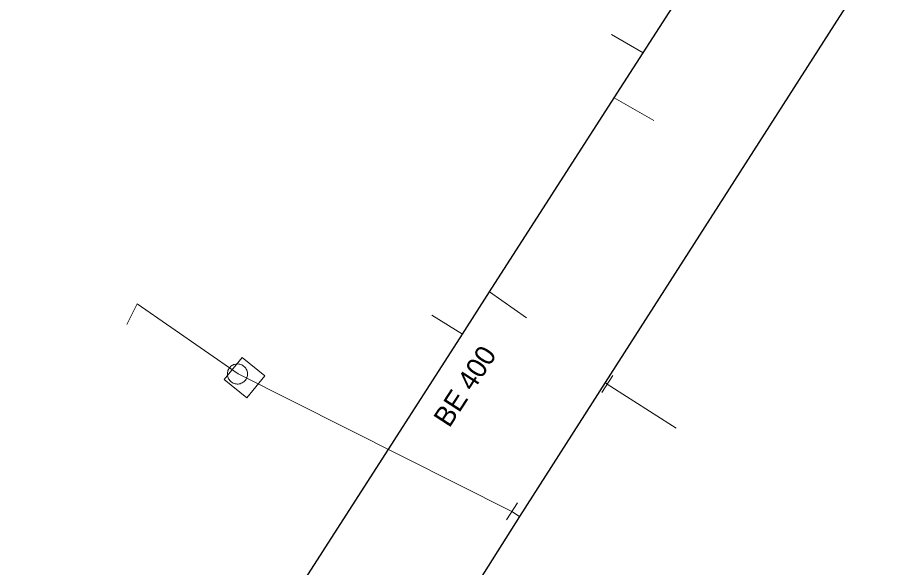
# Model space of a CAD drawing. Extents: x -791337 to -790755, y -988454 to -987923.
# Drawn here: x -791228.7 to -791185.71, y -988043.56 to -988016.22 of the extents above; entities that cross this region are included whole.
import ezdxf

# ---------------------------------------------------------------- set-up
doc = ezdxf.new("R2010")
doc.units = 0
doc.header["$LTSCALE"] = 0.4
for name, color, linetype, lineweight in [('1', 7, 'Continuous', 13), ('11', 7, 'Continuous', 13), ('13', 7, 'Continuous', 13), ('14', 7, 'Continuous', 25), ('17', 7, 'Continuous', 25), ('2', 7, 'Continuous', 13), ('23', 7, 'Continuous', 13), ('34', 7, 'Continuous', 13)]:
    doc.layers.add(name, color=color, linetype=linetype, lineweight=lineweight)

msp = doc.modelspace()

# ---------------------------------------------------------------- linework, layer by layer
at = {"layer": '11'}
for p, q in [((-791199.175, -988017.077), (-791197.614, -988017.994)), ((-791197.071, -988021.344), (-791199.047, -988020.224)), ((-791203.4, -988031.154), (-791205.24, -988029.863)), ((-791208.105, -988031.022), (-791206.587, -988031.96))]:
    msp.add_line(p, q, dxfattribs=at)
at = {"layer": '13'}
for p, q in [((-791204.128, -988040.763), (-791217.731, -988033.931)), ((-791199.39, -988034.44), (-791195.969, -988036.629))]:
    msp.add_line(p, q, dxfattribs=at)
msp.add_lwpolyline([(-791217.731, -988033.931), (-791222.747, -988030.456), (-791223.259, -988031.478)], dxfattribs=at)
at = {"layer": '14', "lineweight": 13}
for p, q in [((-791199.496, -988034.364), (-791199.391, -988034.44)), ((-791203.749, -988041.021), (-791204.128, -988040.763))]:
    msp.add_line(p, q, dxfattribs=at)
at = {"layer": '14'}
msp.add_lwpolyline([(-791220.36, -988053.399), (-791218.616, -988050.685), (-791216.914, -988048.035), (-791206.587, -988031.96), (-791205.24, -988029.863), (-791199.047, -988020.224), (-791197.614, -988017.994), (-791194.219, -988012.71)], dxfattribs=at)
at = {"layer": '17'}
msp.add_lwpolyline([(-791185.71, -988012.8), (-791199.495, -988034.364), (-791203.749, -988041.021), (-791211.533, -988053.348), (-791221.416, -988069.009), (-791228.785, -988080.667), (-791231.254, -988084.482), (-791262.91, -988133.899)], dxfattribs=at)
at = {"layer": '2'}
msp.add_lwpolyline([(-791217.526, -988033.113), (-791218.419, -988034.204), (-791217.293, -988035.125), (-791216.401, -988034.033)], close=True, dxfattribs=at)
at = {"layer": '23'}
for points in [[(-791217.338, -988034.201), (-791217.312, -988034.155), (-791217.291, -988034.106), (-791217.278, -988034.057), (-791217.267, -988034.006), (-791217.263, -988033.954), (-791217.265, -988033.901), (-791217.271, -988033.849), (-791217.283, -988033.799), (-791217.3, -988033.749), (-791217.322, -988033.702), (-791217.348, -988033.656), (-791217.381, -988033.614), (-791217.416, -988033.576), (-791217.455, -988033.543), (-791217.498, -988033.513), (-791217.545, -988033.487), (-791217.592, -988033.467), (-791217.644, -988033.452), (-791217.693, -988033.442), (-791217.746, -988033.437), (-791217.799, -988033.439), (-791217.851, -988033.445), (-791217.902, -988033.458), (-791217.952, -988033.474), (-791217.998, -988033.496), (-791218.043, -988033.524), (-791218.084, -988033.555), (-791218.123, -988033.591), (-791218.156, -988033.631), (-791218.187, -988033.674), (-791218.212, -988033.719), (-791218.233, -988033.768), (-791218.248, -988033.818), (-791218.258, -988033.869), (-791218.261, -988033.92), (-791218.26, -988033.973), (-791218.254, -988034.025), (-791218.242, -988034.077), (-791218.225, -988034.126)], [(-791217.644, -988033.452), (-791217.693, -988033.442), (-791217.746, -988033.437), (-791217.799, -988033.439), (-791217.851, -988033.445), (-791217.902, -988033.458), (-791217.952, -988033.474), (-791217.998, -988033.496), (-791218.043, -988033.524), (-791218.084, -988033.555), (-791218.123, -988033.591), (-791218.156, -988033.631), (-791218.187, -988033.674), (-791218.212, -988033.719), (-791218.233, -988033.768), (-791218.248, -988033.818), (-791218.258, -988033.869), (-791218.261, -988033.92), (-791218.26, -988033.973), (-791218.254, -988034.025), (-791218.242, -988034.077), (-791218.225, -988034.126), (-791218.204, -988034.173), (-791218.176, -988034.218), (-791218.145, -988034.26), (-791218.108, -988034.298), (-791218.069, -988034.331), (-791218.026, -988034.362), (-791217.98, -988034.386), (-791217.932, -988034.407), (-791217.882, -988034.423), (-791217.83, -988034.432), (-791217.778, -988034.437), (-791217.727, -988034.436), (-791217.674, -988034.428), (-791217.623, -988034.418), (-791217.574, -988034.4), (-791217.526, -988034.378), (-791217.481, -988034.351), (-791217.44, -988034.319)], [(-791218.225, -988034.126), (-791218.204, -988034.173), (-791218.176, -988034.218), (-791218.145, -988034.26), (-791218.108, -988034.298), (-791218.069, -988034.331), (-791218.026, -988034.362), (-791217.98, -988034.386), (-791217.932, -988034.407), (-791217.882, -988034.423), (-791217.83, -988034.432), (-791217.778, -988034.437), (-791217.727, -988034.436), (-791217.674, -988034.428), (-791217.623, -988034.418), (-791217.574, -988034.4), (-791217.526, -988034.378), (-791217.481, -988034.351), (-791217.44, -988034.319), (-791217.402, -988034.282), (-791217.368, -988034.244), (-791217.338, -988034.201), (-791217.312, -988034.155), (-791217.291, -988034.106), (-791217.278, -988034.057), (-791217.267, -988034.006), (-791217.263, -988033.954), (-791217.265, -988033.901), (-791217.271, -988033.849), (-791217.283, -988033.799), (-791217.3, -988033.749), (-791217.322, -988033.702), (-791217.348, -988033.656), (-791217.381, -988033.614), (-791217.416, -988033.576), (-791217.455, -988033.543), (-791217.498, -988033.513), (-791217.545, -988033.487), (-791217.592, -988033.467), (-791217.644, -988033.452)], [(-791217.44, -988034.319), (-791217.402, -988034.282), (-791217.368, -988034.244), (-791217.338, -988034.201)]]:
    msp.add_lwpolyline(points, dxfattribs=at)
at = {"layer": '34'}
for p, q in [((-791199.12, -988034.018), (-791199.66, -988034.86)), ((-791203.859, -988040.34), (-791204.396, -988041.184))]:
    msp.add_line(p, q, dxfattribs=at)

# ---------------------------------------------------------------- texts
at = {"layer": '1'}
msp.add_text('BE 400', height=1, rotation=57, dxfattribs=at).set_placement((-791207.24, -988036.651))

doc.saveas('drawing.dxf')
